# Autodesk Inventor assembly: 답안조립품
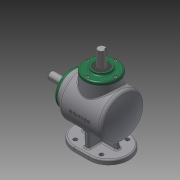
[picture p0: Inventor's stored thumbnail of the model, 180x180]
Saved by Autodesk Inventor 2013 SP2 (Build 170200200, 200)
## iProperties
Created: 2023-01
Part Number: 답안조립품
Document SubType Name: Assembly
Designer: i
Author: i
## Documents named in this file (14)
- C:\Users\i\Desktop\730106V1026\답안조립품.iam
- C:\Users\i\Desktop\730106V1026\본체.ipt
- C:\Users\i\Desktop\730106V1026\M4.ipt
- C:\Users\i\Desktop\730106V1026\메인 베벨기어.ipt
- C:\Users\i\Desktop\730106V1026\메인 축.ipt
- 메인 축.ipt
- C:\Users\i\Desktop\730106V1026\베어링 6203.ipt
- C:\Users\i\Desktop\730106V1026\서브 베벨기어.ipt
- C:\Users\i\Desktop\730106V1026\서브 축.ipt
- 서브 축.ipt
- C:\Users\i\Desktop\730106V1026\오일실 17 32 8.ipt
- C:\Users\i\Desktop\730106V1026\커버.ipt
- C:\Users\i\Desktop\730106V1026\키 4x4.ipt
- C:\Users\i\Desktop\730106V1026\키 5x5.ipt
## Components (8 placed, 1 different names)
1. M4:1
2. M4:3
3. M4:4
4. M4:5
5. M4:2
6. M4:6
7. M4:7
8. M4:8
